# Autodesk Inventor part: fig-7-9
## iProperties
Shininess: 77.0
Angle Display Precision: 2
Document Length Units: 11269
Document Angle Units: 11279
Document Time Units: 11290
Document Mass Units: 11283
Document Length Units Precision: 3
Document Angle Units Precision: 2
Created: 2001-12
Part Number: fig-7-9
Document SubType Name: Modeling
Designer: CADSoft
Density: 0.0
Volumn: 0.0
Area: 0.0
PropertySet Name: Model Information
Control State: 0
Master: False
Checked Out: False
Author: CADSoft
